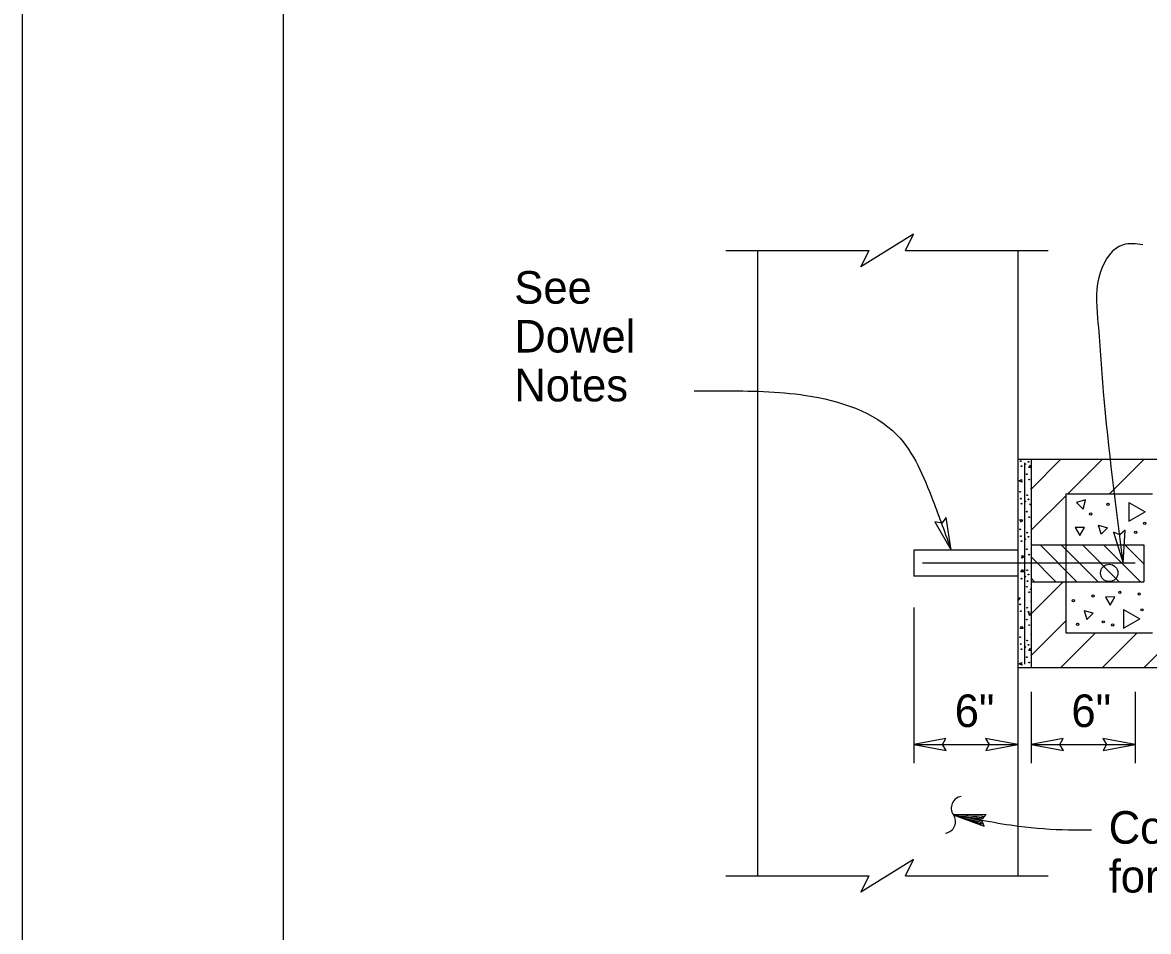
# Model space of a CAD drawing. Extents: x 0 to 2.83, y -0.03 to 1.83.
# Drawn here: x 0 to 0.4501, y 1.1066 to 1.4699 of the extents above; entities that cross this region are included whole.
import ezdxf

# ---------------------------------------------------------------- set-up
doc = ezdxf.new("R2010")
doc.units = 0
for name, color, linetype in [('50', 7, 'Continuous'), ('51', 7, 'Continuous'), ('52', 7, 'Continuous'), ('54', 7, 'Continuous'), ('55', 7, 'Continuous'), ('57', 7, 'Continuous'), ('58', 7, 'Continuous'), ('63', 7, 'Continuous')]:
    doc.layers.add(name, color=color, linetype=linetype)

msp = doc.modelspace()

# ---------------------------------------------------------------- linework, layer by layer
at = {"layer": '50'}
for p, q in [((0.2937337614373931, 1.378767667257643), (0.2937337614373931, 1.1287676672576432)), ((0.3979004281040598, 1.378767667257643), (0.3979004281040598, 1.1287676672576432)), ((0.3979004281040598, 1.295417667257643), (0.5141754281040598, 1.295417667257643)), ((0.4005045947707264, 1.293905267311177), (0.4005045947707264, 1.2134481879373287)), ((0.4031087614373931, 1.295417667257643), (0.4031087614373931, 1.212117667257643)), ((0.41699209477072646, 1.2815343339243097), (0.45170876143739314, 1.2815343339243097)), ((0.41699209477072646, 1.2815343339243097), (0.41699209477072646, 1.2628838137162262)), ((0.4031087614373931, 1.2611477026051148), (0.44824139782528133, 1.2611477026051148)), ((0.4067252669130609, 1.2611477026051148), (0.42148533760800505, 1.2463876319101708)), ((0.4151888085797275, 1.2611477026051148), (0.42994887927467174, 1.2463876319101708)), ((0.41699209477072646, 1.2628838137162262), (0.41699209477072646, 1.2446515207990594)), ((0.4236523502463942, 1.2611477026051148), (0.4384124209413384, 1.2463876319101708)), ((0.4321158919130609, 1.2611477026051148), (0.44687596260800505, 1.2463876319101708)), ((0.4405794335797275, 1.2611477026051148), (0.44824139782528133, 1.2534857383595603)), ((0.44824139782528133, 1.2611477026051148), (0.44824139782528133, 1.2463876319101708)), ((0.3562337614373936, 1.2589760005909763), (0.3562337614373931, 1.2485593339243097)), ((0.3979004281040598, 1.2589760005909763), (0.3562337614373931, 1.2589760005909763)), ((0.4031087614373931, 1.2563006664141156), (0.4130217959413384, 1.2463876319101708)), ((0.3979004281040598, 1.2485593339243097), (0.3562337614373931, 1.2485593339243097)), ((0.4031087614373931, 1.2478371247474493), (0.40455825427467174, 1.2463876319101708)), ((0.4031087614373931, 1.2463876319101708), (0.44824139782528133, 1.2463876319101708)), ((0.41699209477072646, 1.2446515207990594), (0.41699209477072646, 1.2260010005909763)), ((0.41699209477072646, 1.2260010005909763), (0.45170876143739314, 1.2260010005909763)), ((0.3979004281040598, 1.212117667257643), (0.5141754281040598, 1.212117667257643))]:
    msp.add_line(p, q, dxfattribs=at)
for centre in [(0.4270099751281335, 1.273478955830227), (0.4339326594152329, 1.2772831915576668), (0.4485473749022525, 1.2697674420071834), (0.4449671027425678, 1.266172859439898), (0.43861037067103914, 1.242178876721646), (0.42005259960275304, 1.2388094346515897), (0.42790139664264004, 1.2406368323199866), (0.44634684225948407, 1.2414784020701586), (0.4474223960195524, 1.2351418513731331), (0.4217224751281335, 1.229291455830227), (0.4319724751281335, 1.230341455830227), (0.4357974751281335, 1.229091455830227)]:
    msp.add_circle(centre, 0.00045797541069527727, dxfattribs=at)
at = {"layer": '51'}
for p, q in [((0.4422754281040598, 1.2780510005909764), (0.4422754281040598, 1.2706010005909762)), ((0.4422754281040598, 1.2780260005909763), (0.4487254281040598, 1.274342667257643)), ((0.4422754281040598, 1.2706010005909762), (0.4487254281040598, 1.2743093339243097)), ((0.44476917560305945, 1.253767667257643), (0.3597059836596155, 1.253767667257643)), ((0.3562337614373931, 1.2361298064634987), (0.3562337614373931, 1.1738652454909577)), ((0.4401254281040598, 1.2353093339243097), (0.44014209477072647, 1.2278593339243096)), ((0.44014209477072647, 1.235292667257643), (0.44657542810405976, 1.2316010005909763)), ((0.44014209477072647, 1.2278593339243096), (0.44657542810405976, 1.2315760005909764)), ((0.4031087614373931, 1.202420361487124), (0.4031087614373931, 1.1738652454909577)), ((0.44476917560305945, 1.202420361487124), (0.44476917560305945, 1.1738652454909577))]:
    msp.add_line(p, q, dxfattribs=at)
msp.add_circle((0.43435631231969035, 1.2498877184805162), 0.0034722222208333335, dxfattribs=at)
at = {"layer": '52'}
for p, q in [((0.4248587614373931, 1.279067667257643), (0.4212587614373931, 1.2780760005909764)), ((0.4238920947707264, 1.2754510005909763), (0.4248587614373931, 1.2790510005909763)), ((0.4212587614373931, 1.2780843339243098), (0.4238920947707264, 1.2754510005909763)), ((0.4207587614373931, 1.2680474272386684), (0.4226254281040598, 1.264814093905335)), ((0.42447542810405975, 1.2680557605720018), (0.42077542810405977, 1.2680307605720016)), ((0.4226254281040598, 1.264814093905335), (0.42449209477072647, 1.2680474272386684)), ((0.43111160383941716, 1.2653439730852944), (0.4301449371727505, 1.2689273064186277)), ((0.4301449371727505, 1.2689273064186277), (0.4337282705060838, 1.267985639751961)), ((0.4337449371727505, 1.2679689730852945), (0.43111160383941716, 1.2653439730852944)), ((0.43656495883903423, 1.2402787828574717), (0.43284829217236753, 1.240262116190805)), ((0.43284829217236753, 1.2402704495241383), (0.43469829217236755, 1.2370454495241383)), ((0.43469829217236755, 1.2370454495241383), (0.43656495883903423, 1.2402704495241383)), ((0.4243920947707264, 1.234817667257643), (0.4253587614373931, 1.231217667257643)), ((0.4279920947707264, 1.233867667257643), (0.4244087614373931, 1.2348093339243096)), ((0.4253587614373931, 1.231217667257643), (0.4279920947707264, 1.2338593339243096))]:
    msp.add_line(p, q, dxfattribs=at)
at = {"layer": '54'}
for points in [[(0.37123923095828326, 1.258976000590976), (0.36915607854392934, 1.2720176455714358), (0.36741828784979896, 1.2698050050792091), (0.3647030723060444, 1.2702873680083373)], [(0.4399035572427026, 1.2537676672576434), (0.4407742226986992, 1.266945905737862), (0.4385877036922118, 1.265175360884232), (0.4360478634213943, 1.266249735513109)], [(0.3562337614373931, 1.181306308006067), (0.3692254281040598, 1.178931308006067), (0.36771709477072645, 1.181306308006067), (0.3690754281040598, 1.183706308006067)], [(0.3979004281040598, 1.181306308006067), (0.3849087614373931, 1.183681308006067), (0.38641709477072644, 1.181306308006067), (0.3850587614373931, 1.1789063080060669)], [(0.4031087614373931, 1.181306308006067), (0.4161004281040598, 1.178931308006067), (0.41459209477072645, 1.181306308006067), (0.4159504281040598, 1.183706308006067)], [(0.44476917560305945, 1.181306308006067), (0.4317775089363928, 1.183681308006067), (0.4332858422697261, 1.181306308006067), (0.4319275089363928, 1.1789063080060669)]]:
    msp.add_lwpolyline(points, close=True, dxfattribs=at)
at = {"layer": '55'}
for p, q in [((0.356144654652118, 1.3852780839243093), (0.33514688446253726, 1.3722572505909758)), ((0.3528836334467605, 1.378767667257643), (0.356144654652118, 1.3852780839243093)), ((0.2810867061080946, 1.378767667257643), (0.33840790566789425, 1.378767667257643)), ((0.33514688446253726, 1.3722572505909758), (0.33840790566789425, 1.378767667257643)), ((0.3528836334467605, 1.378767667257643), (0.40998073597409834, 1.378767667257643)), ((0.3562337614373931, 1.181306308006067), (0.3979004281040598, 1.181306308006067)), ((0.4031087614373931, 1.181306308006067), (0.44476917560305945, 1.181306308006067)), ((0.356144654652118, 1.1352780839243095), (0.33514688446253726, 1.122257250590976)), ((0.3528836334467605, 1.1287676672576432), (0.356144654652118, 1.1352780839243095)), ((0.2810867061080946, 1.1287676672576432), (0.33840790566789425, 1.1287676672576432)), ((0.33514688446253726, 1.122257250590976), (0.33840790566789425, 1.1287676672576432)), ((0.3528836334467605, 1.1287676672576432), (0.40998073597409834, 1.1287676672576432))]:
    msp.add_line(p, q, dxfattribs=at)
for points in [[(0.40218465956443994, 1.291996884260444), (0.4028096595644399, 1.2928952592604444), (0.4031087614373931, 1.2924654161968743)], [(0.4031087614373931, 1.291996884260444), (0.40218465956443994, 1.291996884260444)], [(0.39837840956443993, 1.286747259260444), (0.3993689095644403, 1.287212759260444), (0.39946103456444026, 1.286122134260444), (0.39837840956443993, 1.286747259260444)], [(0.4025212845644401, 1.2773910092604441), (0.4031087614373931, 1.2775503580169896)], [(0.4031087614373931, 1.2768980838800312), (0.4025212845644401, 1.2773910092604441)], [(0.39866665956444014, 1.2712452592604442), (0.3997571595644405, 1.2711531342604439), (0.39929178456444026, 1.270162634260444), (0.39866665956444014, 1.2712452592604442)], [(0.3994721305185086, 1.255790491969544), (0.3995641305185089, 1.2568809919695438), (0.40055475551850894, 1.2564156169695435), (0.3994721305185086, 1.255790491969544)], [(0.3990062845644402, 1.2503643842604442), (0.3996312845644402, 1.2512627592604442), (0.4002564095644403, 1.2503643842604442), (0.3990062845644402, 1.2503643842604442)], [(0.4028162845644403, 1.243376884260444), (0.4031087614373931, 1.243456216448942)], [(0.4031087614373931, 1.2431314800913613), (0.4028162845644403, 1.243376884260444)], [(0.39789209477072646, 1.2400219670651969), (0.39873540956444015, 1.2399457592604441), (0.39793178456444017, 1.2389881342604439)], [(0.39793178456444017, 1.2389881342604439), (0.39789209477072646, 1.2391345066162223)], [(0.4024406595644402, 1.2328926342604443), (0.40224728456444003, 1.2339697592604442), (0.4031087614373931, 1.2338153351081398)], [(0.4031087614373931, 1.2335607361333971), (0.4024406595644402, 1.2328926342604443)], [(0.39873578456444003, 1.2277240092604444), (0.39936078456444, 1.2286223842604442), (0.39998590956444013, 1.2277240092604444), (0.39873578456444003, 1.2277240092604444)], [(0.40218465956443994, 1.218855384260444), (0.4028096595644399, 1.2197537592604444), (0.4031087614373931, 1.2193239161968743)], [(0.4031087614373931, 1.218855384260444), (0.40218465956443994, 1.218855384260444)], [(0.39837840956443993, 1.2136057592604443), (0.3993689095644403, 1.2140712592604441), (0.39946103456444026, 1.2129806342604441), (0.39837840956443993, 1.2136057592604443)], [(0.37205232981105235, 1.1532252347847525), (0.3843650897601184, 1.1486177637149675), (0.3835549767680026, 1.1506597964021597), (0.37502296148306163, 1.1527001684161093), (0.38375783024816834, 1.1516478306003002), (0.3852211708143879, 1.1532900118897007), (0.3720784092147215, 1.1532290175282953)], [(0.37670264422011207, 1.151822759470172), (0.38290550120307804, 1.1504377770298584), (0.383364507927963, 1.1494578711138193), (0.3734794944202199, 1.1529689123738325), (0.3839781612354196, 1.1528274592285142), (0.3831860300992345, 1.1520468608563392), (0.3771616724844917, 1.1529171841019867)]]:
    msp.add_lwpolyline(points, dxfattribs=at)
for centre in [(0.3990484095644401, 1.2945997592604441), (0.39928403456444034, 1.2925883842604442), (0.4007652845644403, 1.293413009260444), (0.4020906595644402, 1.2943052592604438), (0.4014426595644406, 1.289378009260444), (0.4023851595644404, 1.2871985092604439), (0.3988127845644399, 1.2823388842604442), (0.3990484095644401, 1.279599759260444), (0.4007652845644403, 1.2784130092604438), (0.40156053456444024, 1.2809840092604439), (0.4020906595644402, 1.279305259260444), (0.39928403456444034, 1.277588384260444), (0.4014426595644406, 1.2743780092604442), (0.4023851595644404, 1.272198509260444), (0.3988127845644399, 1.267338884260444), (0.3990484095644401, 1.264599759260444), (0.40156053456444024, 1.265984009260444), (0.39928403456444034, 1.2625883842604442), (0.4007652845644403, 1.2634130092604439), (0.4020906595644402, 1.2643052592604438), (0.4014426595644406, 1.2593780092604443), (0.4023851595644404, 1.2571985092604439), (0.39928403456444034, 1.247588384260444), (0.4007652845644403, 1.2484130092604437), (0.40156053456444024, 1.250984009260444), (0.4017313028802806, 1.2466079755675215), (0.4020906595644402, 1.249305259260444), (0.4014426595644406, 1.2443780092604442), (0.4023851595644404, 1.242198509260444), (0.3988127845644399, 1.237338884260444), (0.3990484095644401, 1.234599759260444), (0.40156053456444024, 1.235984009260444), (0.4020906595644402, 1.2343052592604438), (0.4014426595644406, 1.2312365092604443), (0.4023851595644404, 1.229057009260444), (0.3988127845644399, 1.2241973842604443), (0.3990484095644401, 1.2214582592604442), (0.4007652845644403, 1.220271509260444), (0.40156053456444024, 1.222842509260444), (0.4020906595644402, 1.221163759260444), (0.39928403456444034, 1.2194468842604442), (0.4014426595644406, 1.2162365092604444), (0.4023851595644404, 1.2140570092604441)]:
    msp.add_circle(centre, 0.00015017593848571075, dxfattribs=at)
for centre, radius, start, end in [((0.4031509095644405, 1.283575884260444), 0.00015017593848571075, 106.29949940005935, 253.70050059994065), ((0.4031509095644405, 1.2685758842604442), 0.00015017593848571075, 106.29949940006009, 253.70050059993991), ((0.4031509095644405, 1.2385758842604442), 0.00015017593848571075, 106.29949940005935, 253.70050059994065), ((0.4031509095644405, 1.2254343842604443), 0.00015017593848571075, 106.2994994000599, 253.70050059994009), ((0.37592091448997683, 1.1559311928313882), 0.004697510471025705, 98.71007115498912, 215.11614059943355), ((0.36823590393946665, 1.1505268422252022), 0.004697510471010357, 278.7100711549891, 35.11614059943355)]:
    msp.add_arc(centre, radius, start, end, dxfattribs=at)
for points in [[(0.44781053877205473, 1.3810729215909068), (0.4399035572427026, 1.3810729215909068), (0.43086700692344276, 1.3703009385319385), (0.42973743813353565, 1.3516947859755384), (0.4319965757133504, 1.3223166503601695), (0.4399035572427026, 1.2537676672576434)], [(0.2684856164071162, 1.3226726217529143), (0.27953879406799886, 1.3226726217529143), (0.3131077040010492, 1.3208790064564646), (0.34954225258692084, 1.3050951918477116), (0.3638704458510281, 1.2789084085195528), (0.37123923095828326, 1.258976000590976)], [(0.4273282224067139, 1.1470788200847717), (0.41811992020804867, 1.1470788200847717), (0.3981685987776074, 1.14854315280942), (0.372078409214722, 1.1532290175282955)]]:
    msp.add_spline(points, degree=3, dxfattribs=at)
at = {"layer": '58'}
for p, q in [((0.4316754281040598, 1.295417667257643), (0.41778374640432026, 1.2815343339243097)), ((0.44834209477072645, 1.295417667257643), (0.43459209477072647, 1.281667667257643)), ((0.41699209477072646, 1.2807343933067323), (0.4030587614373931, 1.2668093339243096)), ((0.4159703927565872, 1.2463876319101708), (0.4030587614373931, 1.2334760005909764)), ((0.46564209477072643, 1.2293843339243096), (0.4483754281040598, 1.212117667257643)), ((0.4454587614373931, 1.225867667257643), (0.4317087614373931, 1.212117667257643))]:
    msp.add_line(p, q, dxfattribs=at)
for points in [[(0.41509209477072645, 1.2953843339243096), (0.4031087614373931, 1.2834093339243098)], [(0.4168587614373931, 1.2306093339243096), (0.4030587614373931, 1.2168093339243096)], [(0.42892542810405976, 1.2260010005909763), (0.41504209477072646, 1.212117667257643)]]:
    msp.add_lwpolyline(points, dxfattribs=at)
at = {"layer": '63'}
msp.add_line((0, 0), (0, 1.8333333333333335), dxfattribs=at)
msp.add_lwpolyline([(2.729175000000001, 1.770775), (0.10417500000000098, 1.770775), (0.10417500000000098, 0.06244166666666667), (2.729175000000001, 0.06244166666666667)], close=True, dxfattribs=at)

# ---------------------------------------------------------------- texts
at = {"layer": '57'}
for s, p in [('See', (0.19657606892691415, 1.3575413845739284)), ('Dowel', (0.19657606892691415, 1.3380164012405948)), ('Notes', (0.19657606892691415, 1.3184914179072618)), ('6"', (0.3726184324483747, 1.1882905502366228)), ('6"', (0.41926331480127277, 1.1882905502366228)), ('Concrete Wall (See plans', (0.4341600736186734, 1.1416450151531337)), ('for wall orientation)', (0.4341600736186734, 1.1221200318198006))]:
    msp.add_text(s, height=0.013016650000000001, dxfattribs=at).set_placement(p)

doc.saveas('drawing.dxf')
